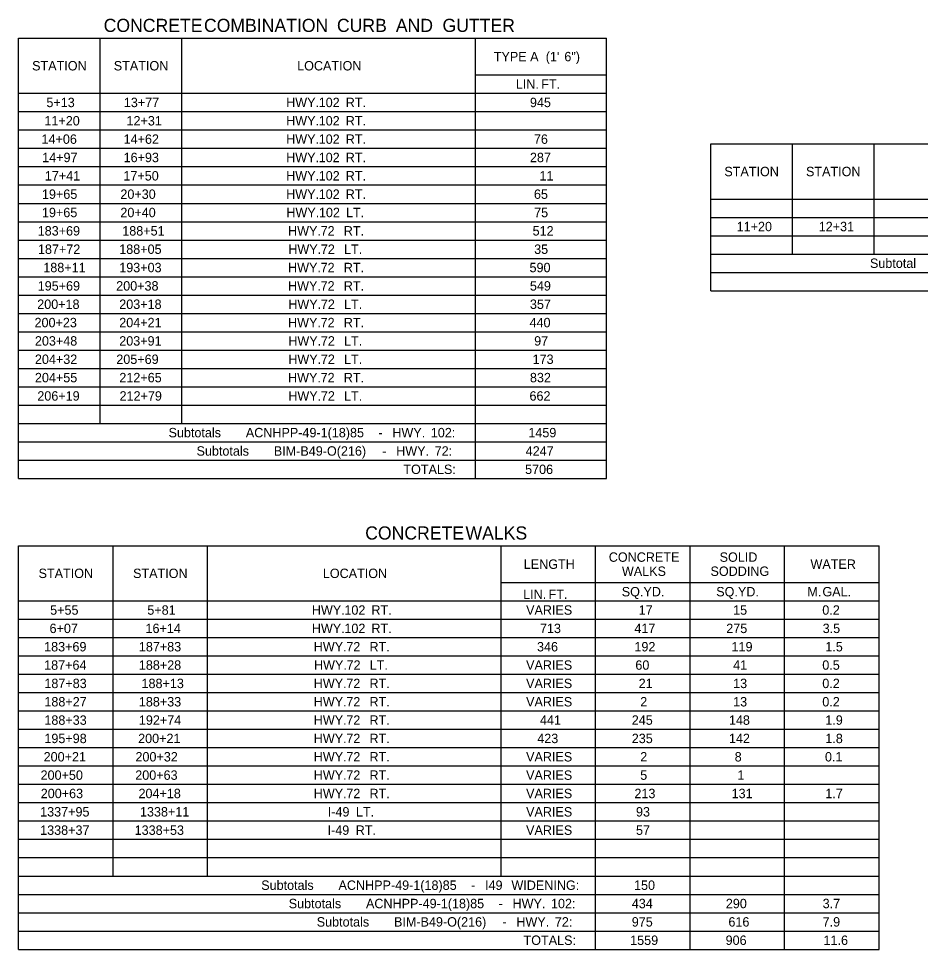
# Model space of a CAD drawing. Extents: x 1226605 to 1228152, y 151309 to 152316.
# Drawn here: x 1227141.4 to 1227620.6, y 151821.5 to 152316.3 of the extents above; entities that cross this region are included whole.
import ezdxf

# ---------------------------------------------------------------- set-up
doc = ezdxf.new("R2010")
doc.units = 0
doc.layers.add('R_Dimension', color=7, linetype='Continuous')

msp = doc.modelspace()

# ---------------------------------------------------------------- linework, layer by layer
at = {"layer": 'R_Dimension'}
for p, q in [((1227141.41, 152305.82), (1227453.9, 152305.82)), ((1227141.41, 152071.82), (1227141.41, 152305.82)), ((1227184.8, 152101.07), (1227184.8, 152305.82)), ((1227228.18, 152101.07), (1227228.18, 152305.82)), ((1227384.18, 152071.82), (1227384.18, 152305.82)), ((1227453.9, 152071.82), (1227453.9, 152305.82)), ((1227384.18, 152286.32), (1227453.9, 152286.32)), ((1227141.41, 152276.57), (1227453.9, 152276.57)), ((1227141.41, 152266.82), (1227453.9, 152266.82)), ((1227141.41, 152257.07), (1227453.9, 152257.07)), ((1227509.27, 152249.62), (1227821.75, 152249.62)), ((1227509.27, 152171.62), (1227509.27, 152249.62)), ((1227552.65, 152191.12), (1227552.65, 152249.62)), ((1227596.04, 152191.12), (1227596.04, 152249.62)), ((1227141.41, 152247.32), (1227453.9, 152247.32)), ((1227141.41, 152237.57), (1227453.9, 152237.57)), ((1227141.41, 152227.82), (1227453.9, 152227.82)), ((1227509.27, 152220.37), (1227821.75, 152220.37)), ((1227141.41, 152218.07), (1227453.9, 152218.07)), ((1227509.27, 152210.62), (1227821.75, 152210.62)), ((1227141.41, 152208.32), (1227453.9, 152208.32)), ((1227509.27, 152200.87), (1227821.75, 152200.87)), ((1227141.41, 152198.57), (1227453.9, 152198.57)), ((1227509.27, 152191.12), (1227821.75, 152191.12)), ((1227141.41, 152188.82), (1227453.9, 152188.82)), ((1227509.27, 152181.37), (1227821.75, 152181.37)), ((1227141.41, 152179.07), (1227453.9, 152179.07)), ((1227509.27, 152171.62), (1227821.75, 152171.62)), ((1227141.41, 152169.32), (1227453.9, 152169.32)), ((1227141.41, 152159.57), (1227453.9, 152159.57)), ((1227141.41, 152149.82), (1227453.9, 152149.82)), ((1227141.41, 152140.07), (1227453.9, 152140.07)), ((1227141.41, 152130.32), (1227453.9, 152130.32)), ((1227141.41, 152120.57), (1227453.9, 152120.57)), ((1227141.41, 152110.82), (1227453.9, 152110.82)), ((1227141.41, 152101.07), (1227453.9, 152101.07)), ((1227141.41, 152091.32), (1227453.9, 152091.32)), ((1227141.41, 152081.57), (1227453.9, 152081.57)), ((1227141.41, 152071.82), (1227453.9, 152071.82)), ((1227141.41, 152036.04), (1227598.68, 152036.04)), ((1227141.41, 151821.54), (1227141.41, 152036.04)), ((1227191.62, 151860.54), (1227191.62, 152036.04)), ((1227241.83, 151860.54), (1227241.83, 152036.04)), ((1227397.83, 151860.54), (1227397.83, 152036.04)), ((1227448.05, 151821.54), (1227448.05, 152036.04)), ((1227498.26, 151821.54), (1227498.26, 152036.04)), ((1227548.47, 151821.54), (1227548.47, 152036.04)), ((1227598.68, 151821.54), (1227598.68, 152036.04)), ((1227397.83, 152016.54), (1227598.68, 152016.54)), ((1227141.41, 152006.79), (1227598.68, 152006.79)), ((1227141.41, 151997.04), (1227598.68, 151997.04)), ((1227141.41, 151987.29), (1227598.68, 151987.29)), ((1227141.41, 151977.54), (1227598.68, 151977.54)), ((1227141.41, 151967.79), (1227598.68, 151967.79)), ((1227141.41, 151958.04), (1227598.68, 151958.04)), ((1227141.41, 151948.29), (1227598.68, 151948.29)), ((1227141.41, 151938.54), (1227598.68, 151938.54)), ((1227141.41, 151928.79), (1227598.68, 151928.79)), ((1227141.41, 151919.04), (1227598.68, 151919.04)), ((1227141.41, 151909.29), (1227598.68, 151909.29)), ((1227141.41, 151899.54), (1227598.68, 151899.54)), ((1227141.41, 151889.79), (1227598.68, 151889.79)), ((1227141.41, 151880.04), (1227598.68, 151880.04)), ((1227141.41, 151870.29), (1227598.68, 151870.29)), ((1227141.41, 151860.54), (1227598.68, 151860.54)), ((1227141.41, 151850.79), (1227598.68, 151850.79)), ((1227141.41, 151841.04), (1227598.68, 151841.04)), ((1227141.41, 151831.29), (1227598.68, 151831.29)), ((1227141.41, 151821.54), (1227598.68, 151821.54))]:
    msp.add_line(p, q, dxfattribs=at)

# ---------------------------------------------------------------- texts
for s, height, p in [('CONCRETE', 7, (1227186.59, 152309.15)), (' COMBINATION', 7, (1227237.3, 152309.15)), (' CURB', 7, (1227307.96, 152309.15)), (' AND', 7, (1227339.27, 152309.15)), (' GUTTER', 7, (1227364.07, 152309.15)), ('TYPE', 5, (1227393.92, 152293.57)), (' A', 5, (1227411.4, 152293.57)), (" (1'", 5, (1227419.67, 152293.57)), (' 6")', 5, (1227429.55, 152293.57)), ('STATION', 5, (1227148.59, 152288.7)), ('STATION', 5, (1227191.98, 152288.7)), ('LOCATION', 5, (1227289.43, 152288.7)), ('LIN.', 5, (1227405.63, 152278.95)), (' FT.', 5, (1227417.29, 152278.95)), ('5+13', 5, (1227156.17, 152269.2)), ('13+77', 5, (1227197.32, 152269.2)), ('HWY.', 5, (1227283.59, 152269.2)), (' 102', 5, (1227299.02, 152269.2)), (' RT.', 5, (1227313.39, 152269.2)), ('945', 5, (1227413.13, 152269.2)), ('11+20', 5, (1227155.13, 152259.45)), ('12+31', 5, (1227198.73, 152259.45)), ('HWY.', 5, (1227283.59, 152259.45)), (' 102', 5, (1227299.02, 152259.45)), (' RT.', 5, (1227313.39, 152259.45)), ('14+06', 5, (1227153.59, 152249.7)), ('14+62', 5, (1227197.2, 152249.7)), ('HWY.', 5, (1227283.59, 152249.7)), (' 102', 5, (1227299.02, 152249.7)), (' RT.', 5, (1227313.39, 152249.7)), ('76', 5, (1227415.24, 152249.7)), ('14+97', 5, (1227153.93, 152239.95)), ('16+93', 5, (1227197.2, 152239.95)), ('HWY.', 5, (1227283.59, 152239.95)), (' 102', 5, (1227299.02, 152239.95)), (' RT.', 5, (1227313.39, 152239.95)), ('287', 5, (1227413.13, 152239.95)), ('17+41', 5, (1227155.35, 152230.2)), ('17+50', 5, (1227197.1, 152230.2)), ('HWY.', 5, (1227283.59, 152230.2)), (' 102', 5, (1227299.02, 152230.2)), (' RT.', 5, (1227313.39, 152230.2)), ('11', 5, (1227418.21, 152230.2)), ('STATION', 5, (1227516.45, 152232.49)), ('STATION', 5, (1227559.84, 152232.49)), ('19+65', 5, (1227153.81, 152220.45)), ('20+30', 5, (1227195.49, 152220.45)), ('HWY.', 5, (1227283.59, 152220.45)), (' 102', 5, (1227299.02, 152220.45)), (' RT.', 5, (1227313.39, 152220.45)), ('65', 5, (1227415.26, 152220.45)), ('19+65', 5, (1227153.81, 152210.7)), ('20+40', 5, (1227195.49, 152210.7)), ('HWY.', 5, (1227283.7, 152210.7)), (' 102', 5, (1227299.14, 152210.7)), (' LT.', 5, (1227313.51, 152210.7)), ('75', 5, (1227415.38, 152210.7)), ('183+69', 5, (1227151.55, 152200.95)), ('188+51', 5, (1227196.49, 152200.95)), ('HWY.', 5, (1227284.61, 152200.95)), (' 72', 5, (1227300.04, 152200.95)), (' RT.', 5, (1227312.36, 152200.95)), ('512', 5, (1227414.55, 152200.95)), ('11+20', 5, (1227522.99, 152203.24)), ('12+31', 5, (1227566.59, 152203.24)), ('187+72', 5, (1227151.69, 152191.2)), ('188+05', 5, (1227194.88, 152191.2)), ('HWY.', 5, (1227284.73, 152191.2)), (' 72', 5, (1227300.16, 152191.2)), (' LT.', 5, (1227312.48, 152191.2)), ('35', 5, (1227415.38, 152191.2)), ('188+11', 5, (1227154.52, 152181.45)), ('193+03', 5, (1227194.88, 152181.45)), ('HWY.', 5, (1227284.61, 152181.45)), (' 72', 5, (1227300.04, 152181.45)), (' RT.', 5, (1227312.36, 152181.45)), ('590', 5, (1227412.92, 152181.45)), ('Subtotal', 5, (1227593.82, 152183.74)), ('195+69', 5, (1227151.55, 152171.7)), ('200+38', 5, (1227193.26, 152171.7)), ('HWY.', 5, (1227284.61, 152171.7)), (' 72', 5, (1227300.04, 152171.7)), (' RT.', 5, (1227312.36, 152171.7)), ('549', 5, (1227413.11, 152171.7)), ('200+18', 5, (1227151.29, 152161.95)), ('203+18', 5, (1227194.88, 152161.95)), ('HWY.', 5, (1227284.73, 152161.95)), (' 72', 5, (1227300.16, 152161.95)), (' LT.', 5, (1227312.48, 152161.95)), ('357', 5, (1227413.13, 152161.95)), ('200+23', 5, (1227149.87, 152152.2)), ('204+21', 5, (1227194.88, 152152.2)), ('HWY.', 5, (1227284.61, 152152.2)), (' 72', 5, (1227300.04, 152152.2)), (' RT.', 5, (1227312.36, 152152.2)), ('440', 5, (1227412.92, 152152.2)), ('203+48', 5, (1227150.07, 152142.45)), ('203+91', 5, (1227194.88, 152142.45)), ('HWY.', 5, (1227284.73, 152142.45)), (' 72', 5, (1227300.16, 152142.45)), (' LT.', 5, (1227312.48, 152142.45)), ('97', 5, (1227415.38, 152142.45)), ('204+32', 5, (1227150.07, 152132.7)), ('205+69', 5, (1227193.32, 152132.7)), ('HWY.', 5, (1227284.73, 152132.7)), (' 72', 5, (1227300.16, 152132.7)), (' LT.', 5, (1227312.48, 152132.7)), ('173', 5, (1227414.55, 152132.7)), ('204+55', 5, (1227150.07, 152122.95)), ('212+65', 5, (1227194.95, 152122.95)), ('HWY.', 5, (1227284.61, 152122.95)), (' 72', 5, (1227300.04, 152122.95)), (' RT.', 5, (1227312.36, 152122.95)), ('832', 5, (1227413.13, 152122.95)), ('206+19', 5, (1227151.35, 152113.2)), ('212+79', 5, (1227195.05, 152113.2)), ('HWY.', 5, (1227284.73, 152113.2)), (' 72', 5, (1227300.16, 152113.2)), (' LT.', 5, (1227312.48, 152113.2)), ('662', 5, (1227412.9, 152113.2)), ('Subtotals', 5, (1227221.08, 152093.7)), (' ACNHPP-49-1(18)85', 5, (1227260.29, 152093.7)), (' -', 5, (1227330.72, 152093.7)), (' HWY.', 5, (1227338.16, 152093.7)), (' 102:', 5, (1227358.6, 152093.7)), ('1459', 5, (1227412.29, 152093.7)), ('Subtotals', 5, (1227235.96, 152083.95)), (' BIM-B49-O(216)', 5, (1227275.17, 152083.95)), (' -', 5, (1227332.77, 152083.95)), (' HWY.', 5, (1227340.21, 152083.95)), (' 72:', 5, (1227360.65, 152083.95)), ('4247', 5, (1227410.89, 152083.95)), ('TOTALS:', 5, (1227345.88, 152074.2)), ('5706', 5, (1227410.56, 152074.2)), ('CONCRETE', 7, (1227325.59, 152039.36)), (' WALKS', 7, (1227376.3, 152039.36)), ('CONCRETE', 5, (1227455.04, 152027.54)), ('SOLID', 5, (1227513.94, 152027.54)), ('LENGTH', 5, (1227409.87, 152023.79)), ('WATER', 5, (1227562.22, 152023.79)), ('STATION', 5, (1227152.01, 152018.91)), ('STATION', 5, (1227202.22, 152018.91)), ('LOCATION', 5, (1227303.08, 152018.91)), ('WALKS', 5, (1227462.01, 152020.04)), ('SODDING', 5, (1227509.09, 152020.04)), ('LIN.', 5, (1227409.53, 152007.79)), (' FT.', 5, (1227421.19, 152007.79)), ('SQ.YD.', 5, (1227461.93, 152009.16)), ('SQ.YD.', 5, (1227512.14, 152009.16)), ('M.', 5, (1227560.57, 152009.16)), (' GAL.', 5, (1227566.71, 152009.16)), ('5+55', 5, (1227158.17, 151999.41)), ('5+81', 5, (1227209.8, 151999.41)), ('HWY.', 5, (1227297.24, 151999.41)), (' 102', 5, (1227312.67, 151999.41)), (' RT.', 5, (1227327.04, 151999.41)), ('VARIES', 5, (1227411.09, 151999.41)), ('17', 5, (1227470.91, 151999.41)), ('15', 5, (1227521.12, 151999.41)), ('0.2', 5, (1227568.5, 151999.41)), ('6+07', 5, (1227157.85, 151989.66)), ('16+14', 5, (1227208.85, 151989.66)), ('HWY.', 5, (1227297.24, 151989.66)), (' 102', 5, (1227312.67, 151989.66)), (' RT.', 5, (1227327.04, 151989.66)), ('713', 5, (1227418.45, 151989.66)), ('417', 5, (1227468.66, 151989.66)), ('275', 5, (1227517.46, 151989.66)), ('3.5', 5, (1227568.7, 151989.66)), ('183+69', 5, (1227154.96, 151979.91)), ('187+83', 5, (1227205.31, 151979.91)), ('HWY.', 5, (1227298.26, 151979.91)), (' 72', 5, (1227313.69, 151979.91)), (' RT.', 5, (1227326.01, 151979.91)), ('346', 5, (1227416.9, 151979.91)), ('192', 5, (1227468.66, 151979.91)), ('119', 5, (1227520.27, 151979.91)), ('1.5', 5, (1227570.11, 151979.91)), ('187+64', 5, (1227154.98, 151970.16)), ('188+28', 5, (1227205.31, 151970.16)), ('HWY.', 5, (1227298.38, 151970.16)), (' 72', 5, (1227313.81, 151970.16)), (' LT.', 5, (1227326.13, 151970.16)), ('VARIES', 5, (1227411.09, 151970.16)), ('60', 5, (1227469.16, 151970.16)), ('41', 5, (1227521.12, 151970.16)), ('0.5', 5, (1227568.5, 151970.16)), ('187+83', 5, (1227155.1, 151960.41)), ('188+13', 5, (1227206.73, 151960.41)), ('HWY.', 5, (1227298.26, 151960.41)), (' 72', 5, (1227313.69, 151960.41)), (' RT.', 5, (1227326.01, 151960.41)), ('VARIES', 5, (1227411.09, 151960.41)), ('21', 5, (1227470.91, 151960.41)), ('13', 5, (1227521.12, 151960.41)), ('0.2', 5, (1227568.5, 151960.41)), ('188+27', 5, (1227155.1, 151950.66)), ('188+33', 5, (1227205.31, 151950.66)), ('HWY.', 5, (1227298.26, 151950.66)), (' 72', 5, (1227313.69, 151950.66)), (' RT.', 5, (1227326.01, 151950.66)), ('VARIES', 5, (1227411.09, 151950.66)), ('2', 5, (1227471.74, 151950.66)), ('13', 5, (1227521.12, 151950.66)), ('0.2', 5, (1227568.5, 151950.66)), ('188+33', 5, (1227155.1, 151940.91)), ('192+74', 5, (1227205.31, 151940.91)), ('HWY.', 5, (1227298.26, 151940.91)), (' 72', 5, (1227313.69, 151940.91)), (' RT.', 5, (1227326.01, 151940.91)), ('441', 5, (1227418.45, 151940.91)), ('245', 5, (1227467.25, 151940.91)), ('148', 5, (1227518.88, 151940.91)), ('1.9', 5, (1227570.09, 151940.91)), ('195+98', 5, (1227155.1, 151931.16)), ('200+21', 5, (1227204.92, 151931.16)), ('HWY.', 5, (1227298.26, 151931.16)), (' 72', 5, (1227313.69, 151931.16)), (' RT.', 5, (1227326.01, 151931.16)), ('423', 5, (1227417.03, 151931.16)), ('235', 5, (1227467.25, 151931.16)), ('142', 5, (1227518.88, 151931.16)), ('1.8', 5, (1227570.11, 151931.16)), ('200+21', 5, (1227154.7, 151921.41)), ('200+32', 5, (1227203.5, 151921.41)), ('HWY.', 5, (1227298.26, 151921.41)), (' 72', 5, (1227313.69, 151921.41)), (' RT.', 5, (1227326.01, 151921.41)), ('VARIES', 5, (1227411.09, 151921.41)), ('2', 5, (1227471.74, 151921.41)), ('8', 5, (1227521.95, 151921.41)), ('0.1', 5, (1227569.92, 151921.41)), ('200+50', 5, (1227153.07, 151911.66)), ('200+63', 5, (1227203.38, 151911.66)), ('HWY.', 5, (1227298.26, 151911.66)), (' 72', 5, (1227313.69, 151911.66)), (' RT.', 5, (1227326.01, 151911.66)), ('VARIES', 5, (1227411.09, 151911.66)), ('5', 5, (1227471.74, 151911.66)), ('1', 5, (1227523.37, 151911.66)), ('200+63', 5, (1227153.17, 151901.91)), ('204+18', 5, (1227205.11, 151901.91)), ('HWY.', 5, (1227298.26, 151901.91)), (' 72', 5, (1227313.69, 151901.91)), (' RT.', 5, (1227326.01, 151901.91)), ('VARIES', 5, (1227411.09, 151901.91)), ('213', 5, (1227468.66, 151901.91)), ('131', 5, (1227520.29, 151901.91)), ('1.7', 5, (1227570.11, 151901.91)), ('1337+95', 5, (1227152.85, 151892.16)), ('1338+11', 5, (1227205.9, 151892.16)), ('I-49', 5, (1227305.7, 151892.16)), (' LT.', 5, (1227318.81, 151892.16)), ('VARIES', 5, (1227411.09, 151892.16)), ('93', 5, (1227469.49, 151892.16)), ('1338+37', 5, (1227152.85, 151882.41)), ('1338+53', 5, (1227203.07, 151882.41)), ('I-49', 5, (1227305.58, 151882.41)), (' RT.', 5, (1227318.69, 151882.41)), ('VARIES', 5, (1227411.09, 151882.41)), ('57', 5, (1227469.49, 151882.41)), ('Subtotals', 5, (1227270.33, 151853.16)), (' ACNHPP-49-1(18)85', 5, (1227309.55, 151853.16)), (' I49', 5, (1227387.42, 151853.16)), (' WIDENING:', 5, (1227401.44, 151853.16)), ('150', 5, (1227468.45, 151853.16)), (' -', 5, (1227379.98, 151853.16)), ('Subtotals', 5, (1227284.94, 151843.41)), (' ACNHPP-49-1(18)85', 5, (1227324.15, 151843.41)), (' HWY.', 5, (1227402.03, 151843.41)), (' 102:', 5, (1227422.46, 151843.41)), ('434', 5, (1227467.25, 151843.41)), ('290', 5, (1227517.24, 151843.41)), ('3.7', 5, (1227568.7, 151843.41)), (' -', 5, (1227394.59, 151843.41)), ('Subtotals', 5, (1227299.82, 151833.66)), (' BIM-B49-O(216)', 5, (1227339.04, 151833.66)), (' HWY.', 5, (1227404.07, 151833.66)), (' 72:', 5, (1227424.51, 151833.66)), ('975', 5, (1227467.25, 151833.66)), ('616', 5, (1227518.62, 151833.66)), ('7.9', 5, (1227568.68, 151833.66)), (' -', 5, (1227396.63, 151833.66)), ('TOTALS:', 5, (1227409.74, 151823.91)), ('1559', 5, (1227466.4, 151823.91)), ('906', 5, (1227517.12, 151823.91)), ('11.6', 5, (1227569.15, 151823.91))]:
    msp.add_text(s, height=height, dxfattribs=at).set_placement(p)

doc.saveas('drawing.dxf')
